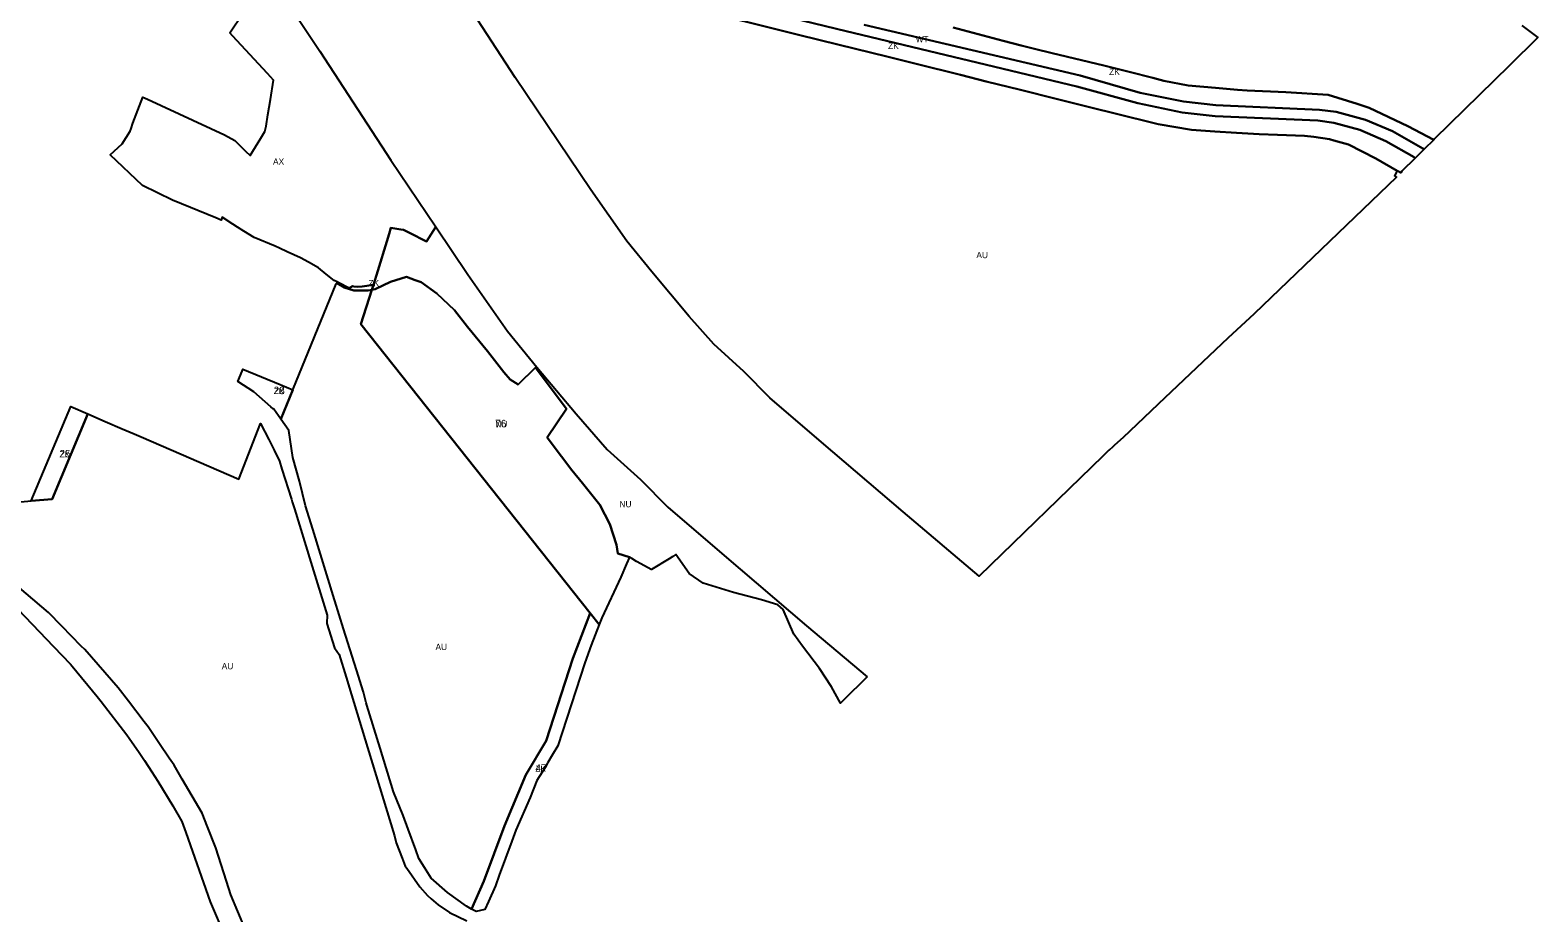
# Model space of a CAD drawing. Extents: x -545779 to -541342, y -1153413 to -1149956.
# Drawn here: x -543834 to -542623, y -1152009 to -1151300 of the extents above; entities that cross this region are included whole.
import ezdxf

# ---------------------------------------------------------------- set-up
doc = ezdxf.new("R2010")
doc.units = 0
for name, color, linetype in [('90640013', 7, 'Continuous'), ('90710013', 7, 'Continuous'), ('90710023', 7, 'Continuous'), ('90730013', 7, 'Continuous'), ('90730023', 7, 'Continuous'), ('90750013', 7, 'Continuous'), ('90760013', 7, 'Continuous'), ('ID_navrh', 7, 'Continuous')]:
    doc.layers.add(name, color=color, linetype=linetype)

msp = doc.modelspace()

# ---------------------------------------------------------------- linework, layer by layer
at = {"layer": '90640013'}
msp.add_lwpolyline([(-543163.961, -1151295.825), (-542990.46, -1151336.67), (-542942.16, -1151350.45), (-542907.51, -1151357.63), (-542881.59, -1151360.47), (-542798.28, -1151364.22), (-542784.83, -1151365.94), (-542761.34, -1151372.15), (-542739.48, -1151381.33), (-542715.21, -1151395.27), (-542714.17, -1151395.87), (-542721.3, -1151402.89), (-542722.29, -1151402.32), (-542744.9, -1151389.26), (-542765.8, -1151380.2), (-542786.61, -1151374.58), (-542799.61, -1151372.78), (-542882, -1151369.27), (-542908.44, -1151366.31), (-542944.02, -1151358.85), (-542992.96, -1151345.36), (-543178.39, -1151301.1), (-543358.41, -1151257.17)], dxfattribs=at)
at = {"layer": '90710013'}
for points in [[(-543358.41, -1151257.17), (-543178.39, -1151301.1), (-542992.96, -1151345.36), (-542944.02, -1151358.85), (-542908.44, -1151366.31), (-542882, -1151369.27), (-542799.61, -1151372.78), (-542786.61, -1151374.58), (-542765.8, -1151380.2), (-542744.9, -1151389.26), (-542722.29, -1151402.32), (-542721.3, -1151402.89), (-542732.07, -1151413.48), (-542732.86, -1151414.83), (-542734.35, -1151413.96), (-542735.72, -1151413.15), (-542752.94, -1151403.28), (-542775.01, -1151392.15), (-542786.61, -1151388.71), (-542790.26, -1151387.63), (-542802.82, -1151385.95), (-542810.18, -1151384.97), (-542832.06, -1151384.22), (-542846.78, -1151383.71), (-542864.78, -1151382.75), (-542882.37, -1151381.53), (-542900.97, -1151380.24), (-542927.73, -1151375.72), (-542933.06, -1151374.39), (-542984.05, -1151361.71), (-543009.67, -1151355.33), (-543038.3, -1151348.21), (-543065.8, -1151341.37), (-543086.44, -1151336.23), (-543122.07, -1151327.37), (-543145.62, -1151321.51), (-543183.89, -1151312.04), (-543216.67, -1151303.95), (-543216.67, -1151303.95), (-543305.78, -1151281.7)], [(-543092.51, -1151297.96), (-543052.23, -1151308.78), (-543037.88, -1151312.63), (-543026.95, -1151315.28), (-543012.97, -1151318.67), (-542971.5, -1151328.73), (-542950.95, -1151333.72), (-542932.08, -1151338.54), (-542923.22, -1151340.8), (-542903.62, -1151344.74), (-542881.71, -1151346.64), (-542864.04, -1151348.18), (-542856.38, -1151348.56), (-542825.29, -1151350.08), (-542791.28, -1151352.06), (-542767.85, -1151359.48), (-542758.26, -1151362.51), (-542727.22, -1151377.28), (-542706.35, -1151388.18), (-542714.17, -1151395.87), (-542715.21, -1151395.27), (-542739.48, -1151381.33), (-542761.34, -1151372.15), (-542784.83, -1151365.94), (-542798.28, -1151364.22), (-542881.59, -1151360.47), (-542907.51, -1151357.63), (-542942.16, -1151350.45), (-542990.46, -1151336.67), (-543163.961, -1151295.825)]]:
    msp.add_lwpolyline(points, dxfattribs=at)
msp.add_lwpolyline([(-543562.19, -1151509.28), (-543573.6, -1151509.37), (-543581.5, -1151506.9), (-543587.43, -1151503.28), (-543587.036, -1151502.434), (-543585.58, -1151503.18), (-543577.47, -1151507.34), (-543574.71, -1151505.84), (-543573.65, -1151506), (-543570.98, -1151506.41), (-543567.07, -1151506.11), (-543557.95, -1151504.85), (-543559.144, -1151508.731), (-543559.144, -1151508.731)], close=True, dxfattribs=at)
at = {"layer": '90710023'}
for points in [[(-543632.879, -1151584.828), (-543632.879, -1151584.828), (-543622.666, -1151589.025), (-543632.3, -1151612.47), (-543637.86, -1151604.63), (-543638.372, -1151604.188), (-543640.19, -1151602.62), (-543653.99, -1151590.76), (-543666.67, -1151582.48), (-543663.37, -1151574.05), (-543662.858, -1151572.696), (-543662.797, -1151572.534)], [(-543832.723, -1151678.258), (-543800.95, -1151602.46), (-543787.28, -1151608.34), (-543815.947, -1151676.729)], [(-543435.52, -1151898.22), (-543419.12, -1151870.85), (-543397.66, -1151804.81), (-543383.805, -1151768.394), (-543376.603, -1151777.475), (-543383.06, -1151794.08), (-543388.23, -1151808.14), (-543409.96, -1151875.02), (-543414.3, -1151882.41), (-543417.79, -1151888.34), (-543420.11, -1151892.3), (-543426.58, -1151902.76), (-543431.92, -1151916.35), (-543443.46, -1151942.7), (-543446.79, -1151951.52), (-543457.05, -1151978.72), (-543459.9, -1151987.3), (-543465.52, -1152000), (-543468.38, -1152006.45), (-543475.35, -1152008.02), (-543479.1, -1152005.99), (-543469.17, -1151983.54), (-543452.76, -1151939.02)]]:
    msp.add_lwpolyline(points, close=True, dxfattribs=at)
at = {"layer": '90730013'}
msp.add_lwpolyline([(-543161.495, -1151819.584), (-543180.59, -1151838.55), (-543182.72, -1151840.56), (-543190.17, -1151827.53), (-543199.69, -1151812.91), (-543213.26, -1151794.85), (-543220.28, -1151785.11), (-543228.8, -1151765.46), (-543233.24, -1151761.72), (-543246.29, -1151757.6), (-543268.84, -1151751.68), (-543293.01, -1151744.18), (-543304.27, -1151736.65), (-543315.01, -1151721.22), (-543317.45, -1151722.93), (-543320.53, -1151724.8), (-543334.68, -1151733.4), (-543334.98, -1151733.24), (-543340.17, -1151730.43), (-543346.65, -1151726.93), (-543350.45, -1151724.58), (-543352.26, -1151723.45), (-543361.78, -1151720.51), (-543362.61, -1151713.54), (-543368.01, -1151696.98), (-543376.03, -1151681.34), (-543390.07, -1151664.07), (-543398.65, -1151653.46), (-543406.97, -1151642.49), (-543418.53, -1151627.26), (-543402.91, -1151604.4), (-543427.2, -1151571.8), (-543427.65, -1151571.22), (-543441.65, -1151584.81), (-543448.01, -1151580.83), (-543453.25, -1151574.82), (-543466.34, -1151558.01), (-543482.25, -1151538.53), (-543492.9, -1151525.06), (-543506.97, -1151511.62), (-543519.6, -1151502.7), (-543524.44, -1151500.91), (-543531.31, -1151498.38), (-543544.32, -1151502.42), (-543556.44, -1151508.25), (-543559.142, -1151508.73), (-543557.95, -1151504.85), (-543554.44, -1151493.44), (-543547.19, -1151469.85), (-543545.33, -1151463.81), (-543543.97, -1151459.057), (-543543.87, -1151459.07), (-543536.02, -1151460.25), (-543533.78, -1151460.57), (-543530.42, -1151462.28), (-543529.02, -1151462.99), (-543515.19, -1151470.03), (-543507.895, -1151458.237), (-543482.123, -1151496.531), (-543450.213, -1151542.021), (-543426.787, -1151570.854), (-543395.205, -1151608.327), (-543370.121, -1151636.856), (-543343.49, -1151660.985), (-543321.453, -1151683.278), (-543276.293, -1151722.188), (-543210.091, -1151778.565)], close=True, dxfattribs=at)
at = {"layer": '90730023'}
msp.add_lwpolyline([(-543361.78, -1151720.51), (-543352.26, -1151723.45), (-543354.57, -1151728.77), (-543359.23, -1151739.5), (-543374.52, -1151772.12), (-543376.603, -1151777.475), (-543383.805, -1151768.394), (-543567.917, -1151536.237), (-543559.142, -1151508.73), (-543556.44, -1151508.25), (-543544.32, -1151502.42), (-543531.31, -1151498.38), (-543524.44, -1151500.91), (-543519.6, -1151502.7), (-543506.97, -1151511.62), (-543492.9, -1151525.06), (-543482.25, -1151538.53), (-543466.34, -1151558.01), (-543453.25, -1151574.82), (-543448.01, -1151580.83), (-543441.65, -1151584.81), (-543427.65, -1151571.22), (-543427.2, -1151571.8), (-543402.91, -1151604.4), (-543418.53, -1151627.26), (-543406.97, -1151642.49), (-543398.65, -1151653.46), (-543390.07, -1151664.07), (-543376.03, -1151681.34), (-543368.01, -1151696.98), (-543362.61, -1151713.54)], close=True, dxfattribs=at)
at = {"layer": '90750013'}
for points in [[(-543305.78, -1151281.7), (-543216.67, -1151303.95), (-543183.89, -1151312.04), (-543145.62, -1151321.51), (-543122.07, -1151327.37), (-543086.44, -1151336.23), (-543065.8, -1151341.37), (-543038.3, -1151348.21), (-543009.67, -1151355.33), (-542984.05, -1151361.71), (-542933.06, -1151374.39), (-542927.73, -1151375.72), (-542900.97, -1151380.24), (-542882.37, -1151381.53), (-542864.78, -1151382.75), (-542846.78, -1151383.71), (-542832.06, -1151384.22), (-542810.18, -1151384.97), (-542802.82, -1151385.95), (-542790.26, -1151387.63), (-542786.61, -1151388.71), (-542775.01, -1151392.15), (-542752.94, -1151403.28), (-542735.72, -1151413.15), (-542737.87, -1151417.23), (-542736.37, -1151418.2), (-542850.69, -1151527.98), (-542871.69, -1151547.61), (-542922.37, -1151595.59), (-542955.86, -1151627.29), (-542962.76, -1151633.49), (-542963.34, -1151634.01), (-542963.9, -1151634.52), (-542967.43, -1151637.69), (-542967.65, -1151637.89), (-542970.14, -1151640.13), (-542972.32, -1151642.24), (-543071.432, -1151738.571), (-543132.489, -1151687.034), (-543198.227, -1151631.052), (-543239.487, -1151595.502), (-543260.47, -1151574.275), (-543284.499, -1151552.504), (-543304.255, -1151530.033), (-543334.333, -1151494.346), (-543354.407, -1151469.639), (-543383.217, -1151428.569), (-543443.977, -1151338.286), (-543500.703, -1151251.262)], [(-542635.662, -1151296.411), (-542622.881, -1151306.054), (-542646.02, -1151328.82), (-542705.74, -1151387.58), (-542706.35, -1151388.18), (-542727.22, -1151377.28), (-542758.26, -1151362.51), (-542767.85, -1151359.48), (-542791.28, -1151352.06), (-542825.29, -1151350.08), (-542856.38, -1151348.56), (-542864.04, -1151348.18), (-542881.71, -1151346.64), (-542903.62, -1151344.74), (-542923.22, -1151340.8), (-542932.08, -1151338.54), (-542950.95, -1151333.72), (-542971.5, -1151328.73), (-543012.97, -1151318.67), (-543026.95, -1151315.28), (-543037.88, -1151312.63), (-543052.23, -1151308.78), (-543092.51, -1151297.96)], [(-543857.563, -1151680.522), (-543832.723, -1151678.258), (-543815.947, -1151676.729), (-543787.28, -1151608.34), (-543773.4, -1151614.36), (-543759.65, -1151620.27), (-543750.15, -1151624.4), (-543744.51, -1151626.74), (-543666.124, -1151660.887), (-543648.69, -1151616.13), (-543641.79, -1151628.89), (-543637.69, -1151637.4), (-543633.38, -1151646.34), (-543631.4, -1151652.63), (-543623.77, -1151676.81), (-543623.089, -1151678.966), (-543621.29, -1151684.66), (-543608.23, -1151727.3), (-543595.18, -1151769.89), (-543595.28, -1151776.41), (-543595.23, -1151776.56), (-543589.24, -1151796.12), (-543585.51, -1151801.47), (-543579.9, -1151819.78), (-543575.59, -1151833.86), (-543562.58, -1151876.34), (-543540.86, -1151947.22), (-543539.72, -1151952.78), (-543534.95, -1151965.03), (-543532.44, -1151971.47), (-543531.08, -1151973.21), (-543520.63, -1151988.01), (-543514.55, -1151995.07), (-543511.5, -1151997.67), (-543505.84, -1152002.5), (-543496.73, -1152008.76), (-543482.99, -1152015.56)], [(-543661.13, -1152021.21), (-543672.46, -1151994.45), (-543675.92, -1151983.71), (-543684.57, -1151956.85), (-543691.1, -1151940.05), (-543695.44, -1151928.88), (-543711.38, -1151901.72), (-543718.05, -1151890.35), (-543721.82, -1151884.77), (-543729.57, -1151873.29), (-543738.74, -1151859.72), (-543741.95, -1151855.55), (-543754.566, -1151839.166), (-543762.98, -1151828.24), (-543789.76, -1151797.63), (-543792.5, -1151794.83), (-543808.08, -1151778.88), (-543818.82, -1151767.88), (-543849.25, -1151741.95)], [(-543843.58, -1151765.07), (-543831.95, -1151777.22), (-543814.68, -1151795.28), (-543801.27, -1151809.3), (-543799.9, -1151810.96), (-543779.82, -1151835.4), (-543776.57, -1151839.36), (-543755.96, -1151866.05), (-543753.93, -1151868.68), (-543746.14, -1151880.29), (-543741.85, -1151886.67), (-543735.78, -1151895.71), (-543730.91, -1151903.16), (-543719.11, -1151923.19), (-543711.73, -1151935.7), (-543708.6, -1151944.53), (-543688.91, -1152000.16), (-543676.4, -1152029.69)]]:
    msp.add_lwpolyline(points, dxfattribs=at)
msp.add_lwpolyline([(-543589.15, -1151757.56), (-543606.61, -1151700.87), (-543612.37, -1151682.17), (-543617.34, -1151662.42), (-543622.57, -1151643.32), (-543625.86, -1151621.57), (-543632.3, -1151612.47), (-543622.666, -1151589.025), (-543587.743, -1151504.042), (-543587.43, -1151503.28), (-543581.5, -1151506.9), (-543573.6, -1151509.37), (-543562.19, -1151509.28), (-543559.144, -1151508.731), (-543559.144, -1151508.731), (-543567.917, -1151536.237), (-543383.805, -1151768.394), (-543397.66, -1151804.81), (-543419.12, -1151870.85), (-543435.52, -1151898.22), (-543452.76, -1151939.02), (-543469.17, -1151983.54), (-543479.1, -1152005.99), (-543483.3, -1152003.71), (-543498.41, -1151992.69), (-543511.62, -1151981.09), (-543516.9, -1151972.68), (-543521.45, -1151965.43), (-543523.99, -1151958.44), (-543530.01, -1151941.87), (-543533.97, -1151930.97), (-543541.88, -1151911.96), (-543552.58, -1151876.88), (-543563.15, -1151842.24), (-543563.68, -1151840.49), (-543565.94, -1151831.89), (-543571.54, -1151813.98), (-543581.86, -1151780.91), (-543588.85, -1151758.53)], close=True, dxfattribs=at)
at = {"layer": '90760013'}
msp.add_lwpolyline([(-543619.594, -1151288.947), (-543601.057, -1151317.058), (-543544.023, -1151404.554), (-543507.895, -1151458.237), (-543515.19, -1151470.03), (-543529.02, -1151462.99), (-543530.42, -1151462.28), (-543533.78, -1151460.57), (-543536.02, -1151460.25), (-543543.87, -1151459.07), (-543543.97, -1151459.057), (-543545.33, -1151463.81), (-543547.19, -1151469.85), (-543554.44, -1151493.44), (-543557.95, -1151504.85), (-543567.07, -1151506.11), (-543570.98, -1151506.41), (-543573.65, -1151506), (-543574.71, -1151505.84), (-543577.47, -1151507.34), (-543585.58, -1151503.18), (-543587.036, -1151502.434), (-543589.52, -1151501.16), (-543595.75, -1151496.21), (-543602.15, -1151491.12), (-543610.18, -1151486.59), (-543616.45, -1151483.05), (-543627.11, -1151478.15), (-543633.23, -1151475.34), (-543636.94, -1151473.63), (-543653.77, -1151466.67), (-543661.98, -1151461.63), (-543667, -1151458.37), (-543670.71, -1151455.96), (-543679.37, -1151450.34), (-543680.2, -1151452.67), (-543684.44, -1151450.94), (-543719.33, -1151436.66), (-543743.38, -1151424.94), (-543769.18, -1151400.33), (-543759.62, -1151391.46), (-543753.2, -1151381.33), (-543752.52, -1151379.28), (-543751.06, -1151374.9), (-543743.07, -1151354.05), (-543739.44, -1151355.73), (-543677.42, -1151384.4), (-543669.09, -1151388.9), (-543668.09, -1151389.92), (-543664.86, -1151393.23), (-543664.49, -1151393.61), (-543660.7, -1151397.48), (-543656.852, -1151400.808), (-543648.379, -1151386.931), (-543645.13, -1151381.61), (-543644.09, -1151377.44), (-543642.58, -1151368.24), (-543640.56, -1151355.87), (-543638.03, -1151340.4), (-543642.93, -1151335.1), (-543670.97, -1151304.78), (-543673.25, -1151302.44), (-543662.86, -1151286.76)], dxfattribs=at)

# ---------------------------------------------------------------- texts
at = {"layer": '90640013'}
msp.add_text('WT', height=5, rotation=0, dxfattribs=at).set_placement((-543122.456, -1151310.023))
at = {"layer": '90710013'}
for rotation, p in [(0, (-543144.651, -1151315.338)), (0, (-542967.114, -1151336.135)), (360, (-543561.919, -1151505.902))]:
    msp.add_text('ZK', height=5, rotation=rotation, dxfattribs=at).set_placement(p)
at = {"layer": '90710023'}
msp.add_text('ZK', height=5, dxfattribs=at).set_placement((-543638.029, -1151592.502))
for rotation, p in [(0, (-543810.002, -1151643.299)), (360, (-543427.851, -1151895.709))]:
    msp.add_text('ZK', height=5, rotation=rotation, dxfattribs=at).set_placement(p)
at = {"layer": '90730013'}
msp.add_text('NU', height=5, rotation=360, dxfattribs=at).set_placement((-543360.319, -1151683.349))
at = {"layer": '90730023'}
msp.add_text('NU', height=5, rotation=360, dxfattribs=at).set_placement((-543460.089, -1151619.121))
at = {"layer": '90750013'}
for rotation, p in [(0, (-543073.736, -1151483.307)), (360, (-543508.052, -1151797.973)), (0, (-543679.715, -1151813.446))]:
    msp.add_text('AU', height=5, rotation=rotation, dxfattribs=at).set_placement(p)
at = {"layer": '90760013'}
msp.add_text('AX', height=5, rotation=0, dxfattribs=at).set_placement((-543638.538, -1151408.236))
at = {"layer": 'ID_navrh'}
for s, p in [('28', (-543638.029, -1151592.502)), ('76', (-543460.089, -1151619.121)), ('25', (-543810.002, -1151643.299)), ('47', (-543427.851, -1151895.709))]:
    msp.add_text(s, height=6, rotation=360, dxfattribs=at).set_placement(p)

doc.saveas('drawing.dxf')
